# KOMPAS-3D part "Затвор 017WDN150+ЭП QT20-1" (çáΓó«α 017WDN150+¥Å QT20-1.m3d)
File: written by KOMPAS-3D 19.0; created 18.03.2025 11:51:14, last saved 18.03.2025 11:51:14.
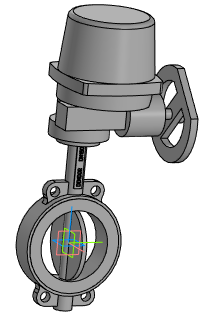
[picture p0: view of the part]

Document properties: Полное имя файла: Затвор 017WDN150+ЭП QT20-1.a3d

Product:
- Part/product: Затвор 017WDN150+ЭП QT20-1
    Масса: 68.0105

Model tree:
1. Операция без истории:1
